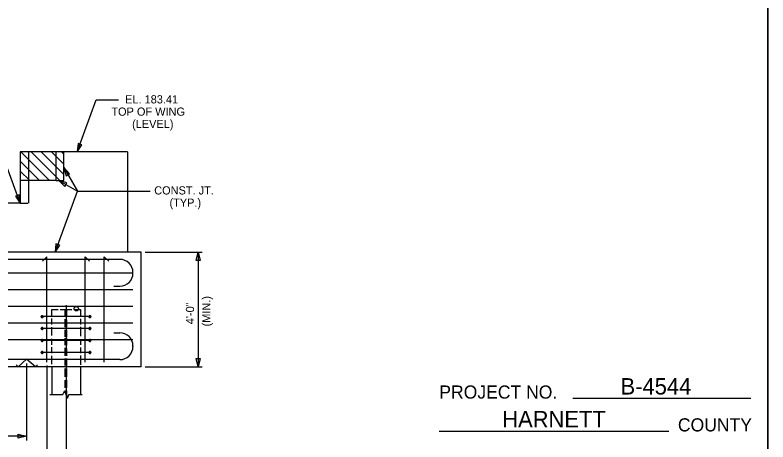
# Model space of a CAD drawing. Extents: x -41 to 191, y -168 to 6.
# Drawn here: x 49.44 to 75.71, y -38.48 to -23.59 of the extents above; entities that cross this region are included whole.
import ezdxf

# ---------------------------------------------------------------- set-up
doc = ezdxf.new("R2010")
doc.units = 0
for name, color, linetype in [('Arrowhead Terminators', 7, 'Continuous'), ('Arrowhead Terminators CELL', 7, 'Continuous'), ('Beam Bolsters CELL', 7, 'Continuous'), ('Dimension Lines', 7, 'Continuous'), ('Mis Object Lines', 7, 'Continuous'), ('Mis Object Lines Hidden', 7, 'Continuous'), ('Plan Sheet CELL', 7, 'Continuous'), ('Plot Shape CELL', 7, 'Continuous'), ('Rebar Lines', 7, 'Continuous'), ('Rebar Lines CELL', 7, 'Continuous'), ('Text', 7, 'Continuous'), ('Title Text', 7, 'Continuous')]:
    doc.layers.add(name, color=color, linetype=linetype)

msp = doc.modelspace()

# ---------------------------------------------------------------- linework, layer by layer
at = {"layer": 'Arrowhead Terminators'}
for points in [[(55.828, -31.86), (55.9, -32.146), (55.757, -32.146)], [(55.828, -35.86), (55.757, -35.574), (55.9, -35.574)]]:
    msp.add_lwpolyline(points, close=True, dxfattribs=at)
at = {"layer": 'Arrowhead Terminators CELL'}
for points in [[(51.606, -28.36), (51.772, -28.116), (51.638, -28.067)], [(51.138, -28.91), (51.219, -29.194), (51.343, -29.122)], [(50.964, -29.361), (51.176, -29.566), (51.248, -29.442)], [(49.619, -30.152), (49.587, -29.858), (49.453, -29.908)], [(50.834, -31.86), (51, -31.616), (50.866, -31.567)], [(49.839, -38.277), (49.552, -38.348), (49.552, -38.205)]]:
    msp.add_lwpolyline(points, close=True, dxfattribs=at)
at = {"layer": 'Beam Bolsters CELL'}
for p, q in [((49.839, -35.589), (49.545, -35.861)), ((50.147, -35.861), (49.839, -35.589)), ((49.545, -35.861), (49.474, -35.79)), ((50.147, -35.861), (50.218, -35.79))]:
    msp.add_line(p, q, dxfattribs=at)
at = {"layer": 'Dimension Lines'}
for p, q in [((50.644, -29.36), (49.644, -28.36)), ((50.998, -29.36), (49.998, -28.36)), ((51.138, -29.146), (50.352, -28.36)), ((51.138, -28.791), (50.705, -28.359)), ((51.138, -28.792), (50.705, -28.36)), ((51.138, -28.439), (51.059, -28.36)), ((50.291, -29.36), (49.619, -28.688)), ((49.949, -29.36), (49.619, -29.029)), ((51.138, -28.91), (51.615, -29.736)), ((50.964, -29.361), (51.615, -29.736)), ((51.615, -29.736), (54.149, -29.736)), ((53.98, -31.86), (55.971, -31.86)), ((55.828, -31.86), (55.828, -35.86)), ((49.839, -35.741), (49.839, -38.426)), ((50.552, -35.81), (50.552, -40.235)), ((51.219, -35.86), (51.219, -43.235)), ((53.98, -35.86), (55.971, -35.86)), ((49.839, -38.277), (43.925, -38.277))]:
    msp.add_line(p, q, dxfattribs=at)
for points in [[(51.606, -28.36), (52.272, -26.549), (53.043, -26.549)], [(49.619, -30.152), (48.738, -27.754), (48.238, -27.754)], [(50.834, -31.86), (51.615, -29.736)]]:
    msp.add_lwpolyline(points, dxfattribs=at)
at = {"layer": 'Mis Object Lines'}
for p, q in [((49.619, -28.361), (49.619, -30.152)), ((53.368, -28.361), (49.619, -28.361)), ((49.918, -30.152), (49.918, -28.361)), ((50.87, -29.361), (50.87, -28.361)), ((51.138, -29.361), (51.138, -28.361)), ((53.368, -28.361), (53.368, -31.86)), ((50.87, -29.36), (49.619, -29.36)), ((50.87, -29.36), (51.138, -29.361)), ((49.619, -30.152), (43.512, -30.152)), ((49.619, -30.152), (49.887, -30.152)), ((53.837, -31.86), (53.368, -31.86)), ((53.837, -35.86), (53.837, -31.86)), ((53.837, -35.86), (47.886, -35.86))]:
    msp.add_line(p, q, dxfattribs=at)
at = {"layer": 'Mis Object Lines Hidden'}
for p, q in [((49.619, -31.86), (12.601, -31.86)), ((53.368, -31.86), (49.619, -31.86))]:
    msp.add_line(p, q, dxfattribs=at)
at = {"layer": 'Plan Sheet CELL'}
for p, q in [((75.694, -0.902), (75.694, -48.992)), ((75.122, -36.969), (68.9, -36.969)), ((72.26, -38.114), (64.245, -38.114))]:
    msp.add_line(p, q, dxfattribs=at)
at = {"layer": 'Plot Shape CELL'}
msp.add_lwpolyline([(0, 0), (75.715, 0), (75.715, -50.38), (0, -50.38)], close=True, dxfattribs=at)
at = {"layer": 'Rebar Lines'}
for p, q in [((50.552, -32.027), (50.399, -32.18)), ((50.552, -35.693), (50.552, -32.027)), ((51.886, -32.027), (52.039, -32.18)), ((51.886, -35.693), (51.886, -32.027)), ((52.552, -35.693), (52.552, -32.027)), ((52.552, -32.027), (52.706, -32.18)), ((53.096, -32.111), (14.053, -32.111)), ((53.554, -32.591), (31.629, -32.591)), ((53.554, -33.174), (31.629, -33.174)), ((53.554, -33.757), (31.629, -33.757)), ((51.187, -34.103), (51.187, -33.86)), ((51.219, -33.709), (51.219, -35.465)), ((51.25, -34.108), (51.25, -33.86)), ((53.554, -34.34), (31.629, -34.34)), ((51.187, -34.474), (51.187, -34.196)), ((51.25, -34.474), (51.25, -34.219)), ((51.187, -34.817), (51.187, -34.567)), ((51.25, -34.829), (51.25, -34.567)), ((53.554, -34.924), (31.629, -34.924)), ((51.187, -35.103), (51.187, -34.86)), ((51.25, -35.108), (51.25, -34.86)), ((51.187, -35.474), (51.187, -35.196)), ((51.25, -35.474), (51.25, -35.219)), ((53.096, -35.61), (13.96, -35.61)), ((51.187, -35.817), (51.187, -35.567)), ((51.219, -35.57), (51.219, -35.86)), ((51.25, -35.829), (51.25, -35.567)), ((50.718, -35.877), (50.718, -36.829)), ((51.187, -36.212), (51.187, -35.916)), ((51.219, -35.93), (51.219, -37.136)), ((51.25, -36.212), (51.25, -35.922)), ((51.72, -35.877), (51.72, -36.829)), ((51.187, -36.595), (51.187, -36.322)), ((51.25, -36.595), (51.25, -36.317)), ((51.187, -36.763), (51.187, -36.689)), ((51.25, -36.913), (51.25, -36.7))]:
    msp.add_line(p, q, dxfattribs=at)
for points in [[(50.718, -34.094), (50.718, -33.86), (50.941, -33.86)], [(51.017, -33.86), (51.416, -33.86)], [(51.486, -33.86), (51.718, -33.86), (51.718, -34.106)], [(50.718, -34.384), (50.718, -34.176)], [(51.718, -34.182), (51.718, -34.381)], [(50.718, -34.771), (50.718, -34.48)], [(51.718, -34.467), (51.718, -34.787)], [(50.718, -35.094), (50.718, -34.886)], [(51.718, -34.892), (51.718, -35.091)], [(50.718, -35.384), (50.718, -35.176)], [(51.718, -35.182), (51.718, -35.381)], [(51.718, -35.467), (51.718, -35.787)], [(50.718, -35.771), (50.718, -35.48)], [(50.649, -36.829), (51.111, -36.829), (51.165, -36.71), (51.267, -36.954), (51.319, -36.829), (51.786, -36.829)]]:
    msp.add_lwpolyline(points, dxfattribs=at)
at = {"layer": 'Rebar Lines CELL'}
for p, q in [((53.554, -32.591), (53.554, -32.57)), ((52.887, -33.049), (53.096, -33.049)), ((52.052, -34.11), (50.386, -34.11)), ((52.052, -34.527), (50.386, -34.527)), ((52.887, -34.672), (53.096, -34.672)), ((52.052, -34.943), (50.386, -34.943)), ((53.554, -35.131), (53.554, -35.152)), ((52.052, -35.36), (50.386, -35.36))]:
    msp.add_line(p, q, dxfattribs=at)
for points in [[(50.386, -34.075), (50.372, -34.077), (50.361, -34.085), (50.353, -34.096), (50.35, -34.11), (50.353, -34.123), (50.361, -34.135), (50.372, -34.142), (50.386, -34.145), (50.399, -34.142), (50.41, -34.135), (50.418, -34.123), (50.421, -34.11), (50.418, -34.096), (50.411, -34.085), (50.399, -34.077), (50.386, -34.075), (50.386, -34.11), (50.386, -34.145), (50.372, -34.142), (50.386, -34.11), (50.361, -34.135), (50.353, -34.123), (50.386, -34.11), (50.35, -34.11), (50.353, -34.096), (50.386, -34.11), (50.361, -34.085), (50.372, -34.077), (50.386, -34.11), (50.399, -34.077), (50.411, -34.085), (50.386, -34.11), (50.418, -34.096), (50.421, -34.11), (50.386, -34.11), (50.418, -34.123), (50.41, -34.135), (50.386, -34.11), (50.399, -34.142)], [(52.052, -34.075), (52.039, -34.077), (52.027, -34.085), (52.02, -34.096), (52.017, -34.11), (52.02, -34.123), (52.027, -34.135), (52.039, -34.142), (52.052, -34.145), (52.066, -34.142), (52.077, -34.135), (52.085, -34.123), (52.088, -34.11), (52.085, -34.096), (52.077, -34.085), (52.066, -34.077), (52.052, -34.075), (52.052, -34.11), (52.052, -34.145), (52.039, -34.142), (52.052, -34.11), (52.027, -34.135), (52.02, -34.123), (52.052, -34.11), (52.017, -34.11), (52.02, -34.096), (52.052, -34.11), (52.027, -34.085), (52.039, -34.077), (52.052, -34.11), (52.066, -34.077), (52.077, -34.085), (52.052, -34.11), (52.085, -34.096), (52.088, -34.11), (52.052, -34.11), (52.085, -34.123), (52.077, -34.135), (52.052, -34.11), (52.066, -34.142)], [(50.386, -34.491), (50.372, -34.494), (50.361, -34.502), (50.353, -34.513), (50.35, -34.527), (50.353, -34.54), (50.361, -34.551), (50.372, -34.559), (50.386, -34.562), (50.399, -34.559), (50.41, -34.551), (50.418, -34.54), (50.421, -34.527), (50.418, -34.513), (50.411, -34.502), (50.399, -34.494), (50.386, -34.491), (50.386, -34.527), (50.386, -34.562), (50.372, -34.559), (50.386, -34.527), (50.361, -34.551), (50.353, -34.54), (50.386, -34.527), (50.35, -34.527), (50.353, -34.513), (50.386, -34.527), (50.361, -34.502), (50.372, -34.494), (50.386, -34.527), (50.399, -34.494), (50.411, -34.502), (50.386, -34.527), (50.418, -34.513), (50.421, -34.527), (50.386, -34.527), (50.418, -34.54), (50.41, -34.551), (50.386, -34.527), (50.399, -34.559)], [(52.052, -34.491), (52.039, -34.494), (52.027, -34.502), (52.02, -34.513), (52.017, -34.527), (52.02, -34.54), (52.027, -34.551), (52.039, -34.559), (52.052, -34.562), (52.066, -34.559), (52.077, -34.551), (52.085, -34.54), (52.088, -34.527), (52.085, -34.513), (52.077, -34.502), (52.066, -34.494), (52.052, -34.491), (52.052, -34.527), (52.052, -34.562), (52.039, -34.559), (52.052, -34.527), (52.027, -34.551), (52.02, -34.54), (52.052, -34.527), (52.017, -34.527), (52.02, -34.513), (52.052, -34.527), (52.027, -34.502), (52.039, -34.494), (52.052, -34.527), (52.066, -34.494), (52.077, -34.502), (52.052, -34.527), (52.085, -34.513), (52.088, -34.527), (52.052, -34.527), (52.085, -34.54), (52.077, -34.551), (52.052, -34.527), (52.066, -34.559)], [(50.386, -34.908), (50.372, -34.911), (50.361, -34.918), (50.353, -34.93), (50.35, -34.943), (50.353, -34.957), (50.361, -34.968), (50.372, -34.976), (50.386, -34.978), (50.399, -34.976), (50.41, -34.968), (50.418, -34.957), (50.421, -34.943), (50.418, -34.93), (50.411, -34.918), (50.399, -34.911), (50.386, -34.908), (50.386, -34.943), (50.386, -34.978), (50.372, -34.976), (50.386, -34.943), (50.361, -34.968), (50.353, -34.957), (50.386, -34.943), (50.35, -34.943), (50.353, -34.93), (50.386, -34.943), (50.361, -34.918), (50.372, -34.911), (50.386, -34.943), (50.399, -34.911), (50.411, -34.918), (50.386, -34.943), (50.418, -34.93), (50.421, -34.943), (50.386, -34.943), (50.418, -34.957), (50.41, -34.968), (50.386, -34.943), (50.399, -34.976)], [(52.052, -34.908), (52.039, -34.911), (52.027, -34.918), (52.02, -34.93), (52.017, -34.943), (52.02, -34.957), (52.027, -34.968), (52.039, -34.976), (52.052, -34.978), (52.066, -34.976), (52.077, -34.968), (52.085, -34.957), (52.088, -34.943), (52.085, -34.93), (52.077, -34.918), (52.066, -34.911), (52.052, -34.908), (52.052, -34.943), (52.052, -34.978), (52.039, -34.976), (52.052, -34.943), (52.027, -34.968), (52.02, -34.957), (52.052, -34.943), (52.017, -34.943), (52.02, -34.93), (52.052, -34.943), (52.027, -34.918), (52.039, -34.911), (52.052, -34.943), (52.066, -34.911), (52.077, -34.918), (52.052, -34.943), (52.085, -34.93), (52.088, -34.943), (52.052, -34.943), (52.085, -34.957), (52.077, -34.968), (52.052, -34.943), (52.066, -34.976)], [(50.386, -35.325), (50.372, -35.327), (50.361, -35.335), (50.353, -35.346), (50.35, -35.36), (50.353, -35.373), (50.361, -35.385), (50.372, -35.392), (50.386, -35.395), (50.399, -35.392), (50.41, -35.385), (50.418, -35.373), (50.421, -35.36), (50.418, -35.346), (50.411, -35.335), (50.399, -35.327), (50.386, -35.325), (50.386, -35.36), (50.386, -35.395), (50.372, -35.392), (50.386, -35.36), (50.361, -35.385), (50.353, -35.373), (50.386, -35.36), (50.35, -35.36), (50.353, -35.346), (50.386, -35.36), (50.361, -35.335), (50.372, -35.327), (50.386, -35.36), (50.399, -35.327), (50.411, -35.335), (50.386, -35.36), (50.418, -35.346), (50.421, -35.36), (50.386, -35.36), (50.418, -35.373), (50.41, -35.385), (50.386, -35.36), (50.399, -35.392)], [(52.052, -35.325), (52.039, -35.327), (52.027, -35.335), (52.02, -35.346), (52.017, -35.36), (52.02, -35.373), (52.027, -35.385), (52.039, -35.392), (52.052, -35.395), (52.066, -35.392), (52.077, -35.385), (52.085, -35.373), (52.088, -35.36), (52.085, -35.346), (52.077, -35.335), (52.066, -35.327), (52.052, -35.325), (52.052, -35.36), (52.052, -35.395), (52.039, -35.392), (52.052, -35.36), (52.027, -35.385), (52.02, -35.373), (52.052, -35.36), (52.017, -35.36), (52.02, -35.346), (52.052, -35.36), (52.027, -35.335), (52.039, -35.327), (52.052, -35.36), (52.066, -35.327), (52.077, -35.335), (52.052, -35.36), (52.085, -35.346), (52.088, -35.36), (52.052, -35.36), (52.085, -35.373), (52.077, -35.385), (52.052, -35.36), (52.066, -35.392)]]:
    msp.add_lwpolyline(points, dxfattribs=at)
msp.add_circle((51.574, -33.834), 0.0773, dxfattribs=at)
for centre, start, end in [((53.096, -32.57), 0, 90), ((53.096, -32.591), 270, 0), ((53.096, -35.131), 0, 90), ((53.096, -35.152), 270, 0)]:
    msp.add_arc(centre, 0.458, start, end, dxfattribs=at)

# ---------------------------------------------------------------- texts
at = {"layer": 'Plan Sheet CELL'}
for s, p in [('PROJECT NO.', (64.245, -36.969)), ('COUNTY', (72.572, -38.114))]:
    msp.add_text(s, height=0.458, dxfattribs=at).set_placement(p)
at = {"layer": 'Text'}
for s, height, p in [('EL. 183.41', 0.286, (53.279, -26.672)), ('TOP OF WING', 0.286, (52.799, -27.101)), ('(LEVEL)', 0.286, (53.523, -27.53)), ('CONST. JT.', 0.286, (54.295, -29.848)), ('(TYP.)', 0.286, (54.828, -30.277)), ('HARNETT', 0.572, (66.442, -37.971))]:
    msp.add_text(s, height=height, dxfattribs=at).set_placement(p)
for s, p in [('4\'-0"', (55.685, -34.374)), ('(MIN.)', (56.257, -34.452))]:
    msp.add_text(s, height=0.286, rotation=90, dxfattribs=at).set_placement(p)
at = {"layer": 'Title Text'}
msp.add_text('B-4544', height=0.572, dxfattribs=at).set_placement((70.572, -36.826))

doc.saveas('drawing.dxf')
